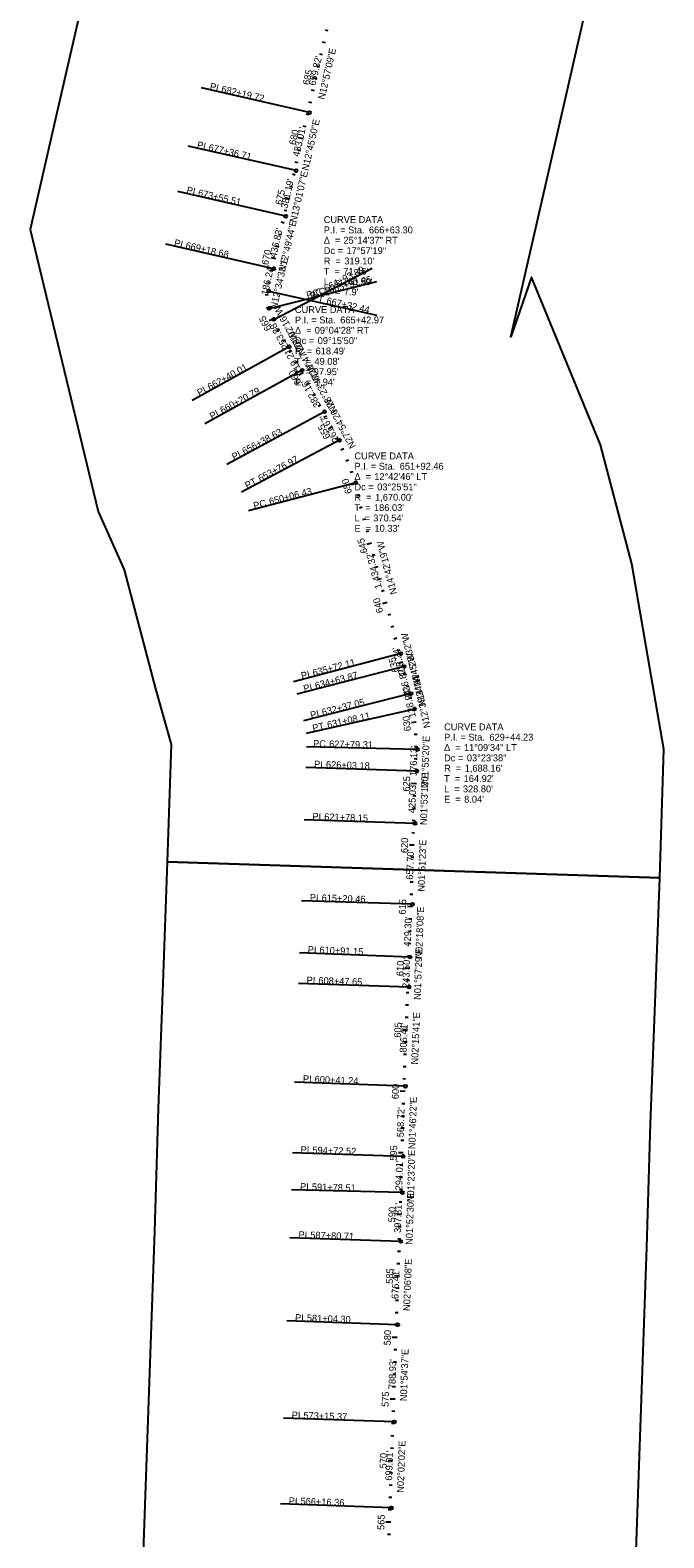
# Model space of a CAD drawing. Extents: x 1697889 to 1709091, y 242468 to 292801.
# Drawn here: x 1700032 to 1705177, y 267842 to 280084 of the extents above; entities that cross this region are included whole.
import ezdxf

# ---------------------------------------------------------------- set-up
doc = ezdxf.new("R2010")
doc.units = 0
for name, color, linetype in [('RD_P_Cells', 7, 'Continuous'), ('SC_Scratch1', 7, 'Continuous'), ('XS_P_Finished_Grade', 7, 'Continuous'), ('XS_P_Headwall', 7, 'Continuous'), ('XS_P_Pavt_Surface', 7, 'Continuous'), ('XS_P_Shoulder_Layers', 7, 'Continuous')]:
    doc.layers.add(name, color=color, linetype=linetype)

msp = doc.modelspace()

# ---------------------------------------------------------------- linework, layer by layer
at = {"layer": 'SC_Scratch1'}
for points in [[(1701146, 273330), (1705144, 273201), (1705177, 274246), (1704918, 275750), (1704664, 276717), (1704104, 278079), (1703936, 277595), (1704158, 278564), (1704379, 279532), (1704601, 280506), (1704826, 281493), (1704931, 281906), (1701431, 283843), (1700923, 282369), (1700703, 281405), (1700481, 280429), (1700257, 279448), (1700032, 278466), (1700585, 276177), (1700795, 275702), (1701049, 274735), (1701177, 274284)], [(1700795, 263352), (1704792, 263192), (1704832, 264197), (1704868, 265207), (1704900, 266199), (1704934, 267197), (1704970, 268198), (1705004, 269201), (1705040, 270202), (1705070, 271205), (1705107, 272187), (1705144, 273201), (1701146, 273330), (1701110, 272345), (1701072, 271329), (1701042, 270333), (1701007, 269335), (1700972, 268339), (1700936, 267341), (1700903, 266340), (1700870, 265333), (1700835, 264345)]]:
    msp.add_lwpolyline(points, close=True, dxfattribs=at)
at = {"layer": 'XS_P_Finished_Grade'}
for p, q in [((1702300, 279415), (1701423, 279617)), ((1702193, 278944), (1701315, 279143)), ((1702107, 278573), (1701230, 278775)), ((1702010, 278147), (1701133, 278347)), ((1701973, 277825), (1702846, 278044)), ((1702011, 277735), (1702810, 278151)), ((1701970, 277965), (1702848, 277769)), ((1702134, 277514), (1701347, 277077)), ((1702240, 277322), (1701451, 276888)), ((1702422, 276986), (1701630, 276558)), ((1702544, 276754), (1701749, 276333)), ((1702677, 276409), (1701806, 276181)), ((1703041, 275022), (1702170, 274793)), ((1703068, 274917), (1702197, 274692)), ((1703124, 274697), (1702252, 274476)), ((1703152, 274571), (1702274, 274374)), ((1703177, 274244), (1702277, 274264)), ((1703171, 274068), (1702271, 274098)), ((1703157, 273643), (1702257, 273673)), ((1703136, 272986), (1702236, 273015)), ((1703118, 272557), (1702219, 272593)), ((1703110, 272314), (1702211, 272344)), ((1703078, 271508), (1702179, 271543)), ((1703061, 270939), (1702161, 270967)), ((1703054, 270645), (1702154, 270667)), ((1703041, 270248), (1702141, 270277)), ((1703016, 269572), (1702116, 269605)), ((1702989, 268783), (1702090, 268813)), ((1702965, 268085), (1702065, 268117))]:
    msp.add_line(p, q, dxfattribs=at)
for centre in [(1702300, 279415), (1702193, 278944), (1702107, 278573), (1702010, 278147), (1701970, 277965), (1701973, 277825), (1702011, 277735), (1702134, 277514), (1702240, 277322), (1702422, 276986), (1702544, 276754), (1702677, 276409), (1703041, 275022), (1703068, 274917), (1703124, 274697), (1703152, 274571), (1703177, 274244), (1703171, 274068), (1703157, 273643), (1703136, 272986), (1703118, 272557), (1703110, 272314), (1703078, 271508), (1703061, 270939), (1703054, 270645), (1703041, 270248), (1703016, 269572), (1702989, 268783), (1702965, 268085)]:
    msp.add_circle(centre, 12, dxfattribs=at)
at = {"layer": 'XS_P_Headwall'}
for p, q in [((1702452, 280078), (1702429, 280083)), ((1702407, 279883), (1702384, 279889)), ((1702430, 279981), (1702406, 279986)), ((1702385, 279786), (1702362, 279791)), ((1702363, 279688), (1702324, 279697)), ((1702318, 279493), (1702294, 279499)), ((1702340, 279591), (1702317, 279596)), ((1702295, 279396), (1702272, 279401)), ((1702273, 279298), (1702250, 279304)), ((1702251, 279201), (1702212, 279210)), ((1702207, 279006), (1702184, 279011)), ((1702229, 279103), (1702206, 279109)), ((1702185, 278908), (1702161, 278914)), ((1702162, 278811), (1702139, 278816)), ((1702140, 278713), (1702101, 278722)), ((1702095, 278518), (1702071, 278524)), ((1702117, 278616), (1702094, 278621)), ((1702073, 278421), (1702049, 278426)), ((1702050, 278323), (1702027, 278329)), ((1702028, 278226), (1701989, 278235)), ((1701984, 278031), (1701961, 278036)), ((1702006, 278128), (1701983, 278134)), ((1701965, 277933), (1701941, 277935)), ((1701971, 277833), (1701948, 277828)), ((1702009, 277741), (1701973, 277723)), ((1702057, 277654), (1702036, 277642)), ((1702105, 277566), (1702084, 277555)), ((1702153, 277479), (1702132, 277467)), ((1702202, 277391), (1702181, 277380)), ((1702250, 277303), (1702214, 277284)), ((1702297, 277216), (1702276, 277204)), ((1702345, 277128), (1702324, 277116)), ((1702392, 277040), (1702371, 277028)), ((1702440, 276951), (1702418, 276940)), ((1702486, 276863), (1702451, 276844)), ((1702533, 276775), (1702512, 276763)), ((1702578, 276685), (1702556, 276675)), ((1702617, 276593), (1702595, 276585)), ((1702651, 276499), (1702628, 276492)), ((1702679, 276403), (1702640, 276393)), ((1702704, 276306), (1702681, 276300)), ((1702729, 276210), (1702706, 276204)), ((1702755, 276113), (1702731, 276107)), ((1702780, 276016), (1702757, 276010)), ((1702805, 275919), (1702767, 275909)), ((1702831, 275823), (1702808, 275817)), ((1702856, 275726), (1702833, 275720)), ((1702882, 275629), (1702858, 275623)), ((1702907, 275533), (1702884, 275526)), ((1702932, 275436), (1702894, 275426)), ((1702958, 275339), (1702935, 275333)), ((1702983, 275242), (1702960, 275236)), ((1703009, 275146), (1702985, 275140)), ((1703034, 275049), (1703011, 275043)), ((1703059, 274952), (1703020, 274942)), ((1703084, 274855), (1703060, 274849)), ((1703108, 274758), (1703085, 274752)), ((1703132, 274661), (1703109, 274656)), ((1703153, 274563), (1703130, 274559)), ((1703167, 274464), (1703128, 274460)), ((1703175, 274365), (1703151, 274364)), ((1703177, 274265), (1703153, 274265)), ((1703174, 274165), (1703150, 274166)), ((1703171, 274065), (1703147, 274066)), ((1703168, 273965), (1703128, 273966)), ((1703161, 273765), (1703137, 273766)), ((1703164, 273865), (1703140, 273866)), ((1703158, 273665), (1703134, 273666)), ((1703154, 273565), (1703130, 273566)), ((1703151, 273465), (1703111, 273467)), ((1703145, 273265), (1703121, 273266)), ((1703148, 273365), (1703124, 273366)), ((1703141, 273165), (1703117, 273166)), ((1703138, 273065), (1703114, 273066)), ((1703135, 272966), (1703095, 272967)), ((1703127, 272766), (1703103, 272767)), ((1703131, 272866), (1703107, 272867)), ((1703123, 272666), (1703099, 272667)), ((1703119, 272566), (1703095, 272567)), ((1703115, 272466), (1703075, 272467)), ((1703112, 272366), (1703088, 272367)), ((1703104, 272166), (1703080, 272167)), ((1703108, 272266), (1703084, 272267)), ((1703100, 272066), (1703076, 272067)), ((1703096, 271966), (1703056, 271968)), ((1703092, 271866), (1703068, 271867)), ((1703085, 271667), (1703061, 271667)), ((1703088, 271766), (1703064, 271767)), ((1703081, 271567), (1703057, 271568)), ((1703077, 271467), (1703037, 271468)), ((1703074, 271367), (1703050, 271367)), ((1703071, 271267), (1703047, 271267)), ((1703065, 271067), (1703041, 271068)), ((1703068, 271167), (1703044, 271168)), ((1703062, 270967), (1703022, 270968)), ((1703059, 270867), (1703035, 270868)), ((1703056, 270767), (1703032, 270768)), ((1703051, 270567), (1703027, 270568)), ((1703054, 270667), (1703030, 270668)), ((1703048, 270467), (1703008, 270468)), ((1703044, 270367), (1703020, 270368)), ((1703041, 270267), (1703017, 270268)), ((1703038, 270167), (1703014, 270168)), ((1703030, 269967), (1702990, 269969)), ((1703034, 270067), (1703010, 270068)), ((1703027, 269867), (1703003, 269868)), ((1703023, 269768), (1702999, 269768)), ((1703019, 269668), (1702995, 269668)), ((1703012, 269468), (1702972, 269469)), ((1703016, 269568), (1702992, 269568)), ((1703009, 269368), (1702985, 269369)), ((1703006, 269268), (1702982, 269269)), ((1703002, 269168), (1702978, 269169)), ((1702999, 269068), (1702975, 269069)), ((1702996, 268968), (1702956, 268969)), ((1702992, 268868), (1702968, 268869)), ((1702989, 268768), (1702965, 268769)), ((1702985, 268668), (1702961, 268669)), ((1702982, 268568), (1702958, 268569)), ((1702978, 268468), (1702938, 268470)), ((1702975, 268368), (1702951, 268369)), ((1702971, 268268), (1702947, 268269)), ((1702968, 268168), (1702944, 268169)), ((1702964, 268069), (1702940, 268069)), ((1702960, 267969), (1702920, 267970)), ((1702957, 267869), (1702933, 267870))]:
    msp.add_line(p, q, dxfattribs=at)

# ---------------------------------------------------------------- texts
at = {"layer": 'RD_P_Cells'}
for s, p in [('CURVE DATA', (1702416, 278518)), ('Δ  = ', (1702416, 278350)), ('P.I. = Sta. ', (1702416, 278434)), ('25°14\'37" RT', (1702576, 278350)), ('666+63.30', (1702783, 278434)), ('Dc = ', (1702416, 278266)), ('17°57\'19"', (1702601, 278266)), ('T  = ', (1702416, 278098)), ('R  = ', (1702416, 278182)), ("71.46'", (1702575, 278098)), ("319.10'", (1702583, 278182)), ('L  = ', (1702416, 278014)), ("140.59'", (1702569, 278014)), ('E  = ', (1702416, 277930)), ("7.9'", (1702579, 277930)), ('CURVE DATA', (1702182, 277787)), ('Δ  = ', (1702182, 277619)), ('P.I. = Sta. ', (1702182, 277703)), ('09°04\'28" RT', (1702343, 277619)), ('665+42.97', (1702550, 277703)), ('Dc = ', (1702182, 277535)), ('09°15\'50"', (1702367, 277535)), ('T  = ', (1702182, 277367)), ('R  = ', (1702182, 277451)), ("49.08'", (1702341, 277367)), ("618.49'", (1702350, 277451)), ('L  = ', (1702182, 277283)), ("97.95'", (1702335, 277283)), ('E  = ', (1702182, 277199)), ("1.94'", (1702345, 277199)), ('CURVE DATA', (1702665, 276599)), ('P.I. = Sta. ', (1702665, 276515)), ('651+92.46', (1703033, 276515)), ('Δ  = ', (1702665, 276431)), ('12°42\'46" LT', (1702826, 276431)), ('Dc = ', (1702665, 276347)), ('R  = ', (1702665, 276263)), ("1,670.00'", (1702833, 276263)), ('03°25\'51"', (1702850, 276347)), ('T  = ', (1702665, 276179)), ("186.03'", (1702824, 276179)), ('L  = ', (1702665, 276095)), ("370.54'", (1702818, 276095)), ('E  = ', (1702665, 276011)), ("10.33'", (1702828, 276011)), ('CURVE DATA', (1703393, 274399)), ('P.I. = Sta. ', (1703393, 274315)), ('629+44.23', (1703761, 274315)), ('Δ  = ', (1703393, 274231)), ('11°09\'34" LT', (1703554, 274231)), ('Dc = ', (1703393, 274147)), ('R  = ', (1703393, 274063)), ("1,688.16'", (1703561, 274063)), ('03°23\'38"', (1703578, 274147)), ('T  = ', (1703393, 273979)), ("164.92'", (1703552, 273979)), ('L  = ', (1703393, 273895)), ('E  = ', (1703393, 273811)), ("328.80'", (1703546, 273895)), ("8.04'", (1703556, 273811))]:
    msp.add_text(s, height=56, dxfattribs=at).set_placement(p)
at = {"layer": 'XS_P_Finished_Grade'}
for s, rotation, p in [('PI', 347.0474, (1701487, 279603)), ('682+19.72', 347.0474, (1701580, 279581)), ('PI', 347.2361, (1701383, 279128)), ('677+36.71', 347.2361, (1701476, 279107)), ('PI', 346.9815, (1701298, 278761)), ('673+55.51', 346.9815, (1701391, 278739)), ('PI', 347.1711, (1701197, 278333)), ('669+18.68', 347.1711, (1701290, 278312)), ('664+93.89', 27.4899, (1702436, 277958)), ('665+91.85', 14.0826, (1702465, 277950)), ('PCC', 14.0826, (1702283, 277904)), ('PC', 27.4899, (1702321, 277897)), ('PT', 347.4242, (1702315, 277889)), ('667+32.44', 347.4242, (1702434, 277862)), ('662+40.01', 29.0379, (1701491, 277158)), ('PI', 29.0379, (1701407, 277111)), ('660+20.79', 28.7888, (1701593, 276967)), ('PI', 28.7888, (1701509, 276921)), ('656+38.63', 28.3963, (1701772, 276635)), ('PI', 28.3963, (1701688, 276590)), ('653+76.97', 27.9071, (1701901, 276415)), ('PT', 27.9071, (1701794, 276358)), ('650+06.43', 14.7052, (1701980, 276227)), ('PC', 14.7052, (1701853, 276194)), ('635+72.11', 14.7052, (1702333, 274837)), ('PI', 14.7052, (1702240, 274813)), ('634+63.87', 14.4755, (1702352, 274733)), ('PI', 14.4755, (1702259, 274709)), ('632+37.05', 14.2458, (1702408, 274516)), ('PI', 14.2458, (1702315, 274493)), ('631+08.11', 12.6595, (1702450, 274415)), ('PT', 12.6595, (1702331, 274388)), ('PC', 358.7438, (1702329, 274264)), ('627+79.31', 358.7438, (1702459, 274261)), ('PI', 358.0779, (1702337, 274097)), ('626+03.18', 358.0779, (1702433, 274094)), ('PI', 358.1134, (1702323, 273672)), ('621+78.15', 358.1134, (1702419, 273669)), ('PI', 358.1436, (1702302, 273014)), ('615+20.46', 358.1436, (1702398, 273011)), ('PI', 357.6977, (1702285, 272591)), ('610+91.15', 357.6977, (1702380, 272588)), ('PI', 358.0418, (1702276, 272343)), ('608+47.65', 358.0418, (1702372, 272340)), ('PI', 357.7385, (1702246, 271542)), ('600+41.24', 357.7385, (1702341, 271538)), ('PI', 358.2272, (1702227, 270966)), ('594+72.52', 358.2272, (1702323, 270963)), ('PI', 358.611, (1702223, 270667)), ('591+78.51', 358.611, (1702319, 270664)), ('PI', 358.1251, (1702210, 270276)), ('587+80.71', 358.1251, (1702306, 270273)), ('PI', 357.8979, (1702182, 269603)), ('581+04.30', 357.8979, (1702278, 269600)), ('PI', 358.0898, (1702155, 268812)), ('573+15.37', 358.0898, (1702250, 268809)), ('PI', 357.966, (1702131, 268115)), ('566+16.36', 357.966, (1702227, 268112))]:
    msp.add_text(s, height=56, rotation=rotation, dxfattribs=at).set_placement(p)
at = {"layer": 'XS_P_Headwall'}
for s, rotation, p in [('685', 77.0474, (1702298, 279635)), ('680', 77.2361, (1702187, 279148)), ('675', 76.9815, (1702075, 278661)), ('670', 77.1711, (1701964, 278173)), ('665', 116.9242, (1701993, 277659)), ('660', 118.3963, (1702236, 277222)), ('655', 117.9071, (1702472, 276781)), ('650', 104.7052, (1702646, 276327)), ('645', 104.7052, (1702773, 275843)), ('640', 104.7052, (1702900, 275359)), ('635', 104.4755, (1703026, 274876)), ('630', 96.234, (1703124, 274394)), ('625', 88.1134, (1703114, 273901)), ('620', 88.1436, (1703098, 273401)), ('615', 87.6977, (1703081, 272902)), ('610', 88.0418, (1703062, 272402)), ('605', 87.7385, (1703043, 271902)), ('600', 88.2272, (1703024, 271403)), ('595', 88.2272, (1703009, 270903)), ('590', 88.1251, (1702995, 270403)), ('585', 87.8979, (1702977, 269903)), ('580', 88.0898, (1702959, 269404)), ('575', 88.0898, (1702942, 268904)), ('570', 87.966, (1702925, 268405)), ('565', 87.9344, (1702907, 267905))]:
    msp.add_text(s, height=56, rotation=rotation, dxfattribs=at).set_placement(p)
at = {"layer": 'XS_P_Pavt_Surface'}
for s, rotation, p in [('N12°57\'09"E', 77.0474, (1702422, 279517)), ('N12°45\'50"E', 77.2361, (1702291, 278940)), ('N13°01\'07"E', 76.9815, (1702193, 278519)), ('N12°49\'44"E', 77.1711, (1702103, 278120)), ('N12°34\'33"E', 77.4242, (1702035, 277817)), ('N29°02\'16"W', 119.0379, (1702272, 277464)), ('N28°47\'20"W', 118.7888, (1702385, 277256)), ('N28°23\'47"W', 118.3963, (1702528, 276991)), ('N27°54\'26"W', 117.9071, (1702679, 276705)), ('N14°42\'19"W', 104.7052, (1703012, 275510)), ('N14°28\'32"W', 104.4755, (1703207, 274764)), ('N14°14\'45"W', 104.2458, (1703247, 274601)), ('N12°39\'34"W', 102.6595, (1703284, 274424)), ('N01°55\'20"E', 88.0779, (1703262, 273929)), ('N01°53\'12"E', 88.1134, (1703253, 273629)), ('N01°51\'23"E', 88.1436, (1703235, 273088)), ('N02°18\'08"E', 87.6977, (1703214, 272544)), ('N01°57\'29"E', 88.0418, (1703203, 272209)), ('N02°15\'41"E', 87.7385, (1703181, 271684)), ('N01°46\'22"E', 88.2272, (1703159, 270997)), ('N01°23\'20"E', 88.611, (1703148, 270567)), ('N01°52\'30"E', 88.1251, (1703136, 270220)), ('N02°06\'08"E', 87.8979, (1703116, 269683)), ('N01°54\'37"E', 88.0898, (1703091, 268951)), ('N02°02\'02"E', 87.966, (1703065, 268207))]:
    msp.add_text(s, height=56, rotation=rotation, dxfattribs=at).set_placement(p)
at = {"layer": 'XS_P_Shoulder_Layers'}
for s, rotation, p in [("699.82'", 77.0474, (1702348, 279630)), ("483.01'", 77.2361, (1702217, 279053)), ("381.19'", 76.9815, (1702120, 278632)), ("436.83'", 77.1711, (1702029, 278233)), ("186.24'", 77.4242, (1701961, 277929)), ("253.88'", 119.0379, (1702135, 277511)), ("219.21'", 118.7888, (1702249, 277304)), ("382.16'", 118.3963, (1702392, 277039)), ("261.67'", 117.9071, (1702543, 276755)), ("1,434.32'", 104.7052, (1702889, 275556)), ("108.24'", 104.4755, (1703086, 274844)), ("226.82'", 104.2458, (1703127, 274681)), ("128.94'", 102.6595, (1703165, 274508)), ("176.13'", 88.0779, (1703169, 274027)), ("425.03'", 88.1134, (1703159, 273726)), ("657.70'", 88.1436, (1703141, 273185)), ("429.30'", 87.6977, (1703121, 272642)), ("243.50'", 88.0418, (1703109, 272306)), ("806.41'", 87.7385, (1703088, 271781)), ("568.72'", 88.2272, (1703065, 271094)), ("294.01'", 88.611, (1703053, 270663)), ("397.81'", 88.1251, (1703042, 270317)), ("676.41'", 87.8979, (1703022, 269780)), ("788.93'", 88.0898, (1702997, 269048)), ("699.01'", 87.966, (1702971, 268305))]:
    msp.add_text(s, height=56, rotation=rotation, dxfattribs=at).set_placement(p)

doc.saveas('drawing.dxf')
